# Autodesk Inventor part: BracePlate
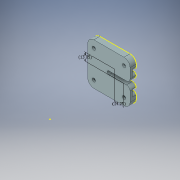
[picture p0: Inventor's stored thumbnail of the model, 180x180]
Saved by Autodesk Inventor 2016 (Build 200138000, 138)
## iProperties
Created: 2016-01
Part Number: BracePlate
Material: Generic
Document SubType Name: Modeling
Designer: John
Density: 1 g/cm^3
Appearance: Default
Author: John
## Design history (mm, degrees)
feature "Base1"
sketch "Sketch1"
  geometry: L1 (-4, 37.62)-(25, 37.62) reference; L2 (25, 32.02)-(-4, 32.02) reference; L3 (-6, 24.02)-(10.75, 24.02) reference; L4 (10.75, 19.52)-(-6, 19.52) reference; L5 (-10, 10)-(-10, 15.52) reference; L6 (50, 0)-(0, 0) reference; L7 (60, 59.64)-(60, 10) reference; L8 (0, 69.64)-(50, 69.64) reference; L9 (-10, 56.12)-(-10, 59.64) reference; L10 (-6, 52.12)-(10.75, 52.12) reference; L11 (10.75, 47.62)-(-6, 47.62) reference; L12 (3.95, 9.691)-(3.95, 14.309) reference; L13 (-0.05, 7.381)-(3.95, 9.691) reference; L14 (-4.05, 9.691)-(-0.05, 7.381) reference; L15 (-4.05, 14.309)-(-4.05, 9.691) reference; L16 (-0.05, 16.619)-(-4.05, 14.309) reference; L17 (3.95, 14.309)-(-0.05, 16.619) reference; L18 (54.05, 9.691)-(54.05, 14.309) reference; L19 (50.05, 7.381)-(54.05, 9.691) reference; L20 (46.05, 9.691)-(50.05, 7.381) reference; L21 (46.05, 14.309)-(46.05, 9.691) reference; L22 (50.05, 16.619)-(46.05, 14.309) reference; L23 (54.05, 14.309)-(50.05, 16.619) reference; L24 (54.05, 55.331)-(54.05, 59.949) reference; L25 (50.05, 53.021)-(54.05, 55.331) reference; L26 (46.05, 55.331)-(50.05, 53.021) reference; L27 (46.05, 59.949)-(46.05, 55.331) reference; L28 (50.05, 62.259)-(46.05, 59.949) reference; L29 (54.05, 59.949)-(50.05, 62.259) reference; L30 (3.95, 59.949)-(-0.05, 62.259) reference; L31 (3.95, 55.331)-(3.95, 59.949) reference; L32 (-0.05, 53.021)-(3.95, 55.331) reference; L33 (-4.05, 55.331)-(-0.05, 53.021) reference; L34 (-4.05, 59.949)-(-4.05, 55.331) reference; L35 (-0.05, 62.259)-(-4.05, 59.949) reference; A1 r 4 centre (-6, 43.62) between (-6, 47.62) and (-10, 43.62) reference; A2 r 6 centre (-4, 43.62) between (-10, 43.62) and (-4, 37.62) reference; A3 r 2.8 centre (25, 34.82) between (25, 32.02) and (25, 37.62) reference; A4 r 6 centre (-4, 26.02) between (-4, 32.02) and (-9.898, 27.122) reference; A5 r 4 centre (-6, 28.02) between (-9.898, 27.122) and (-6, 24.02) reference; A6 r 2.25 centre (10.75, 21.77) between (10.75, 19.52) and (10.75, 24.02) reference; A7 r 4 centre (-6, 15.52) between (-6, 19.52) and (-10, 15.52) reference; A8 r 10 centre (0, 10) between (-10, 10) and (0, 0) reference; A9 r 10 centre (50, 10) between (50, 0) and (60, 10) reference; A10 r 10 centre (50, 59.64) between (60, 59.64) and (50, 69.64) reference; A11 r 10 centre (0, 59.64) between (0, 69.64) and (-10, 59.64) reference; A12 r 4 centre (-6, 56.12) between (-10, 56.12) and (-6, 52.12) reference; A13 r 2.25 centre (10.75, 49.87) between (10.75, 47.62) and (10.75, 52.12) reference; 1 further point
  dimensions: "d0" = 14.25 horizontal distance of A3.centre A6.centre (derived); "d1" = 13.05 vertical distance of A3.centre A6.centre (derived)
  node "Projected Loop1"
body "Solid1"
